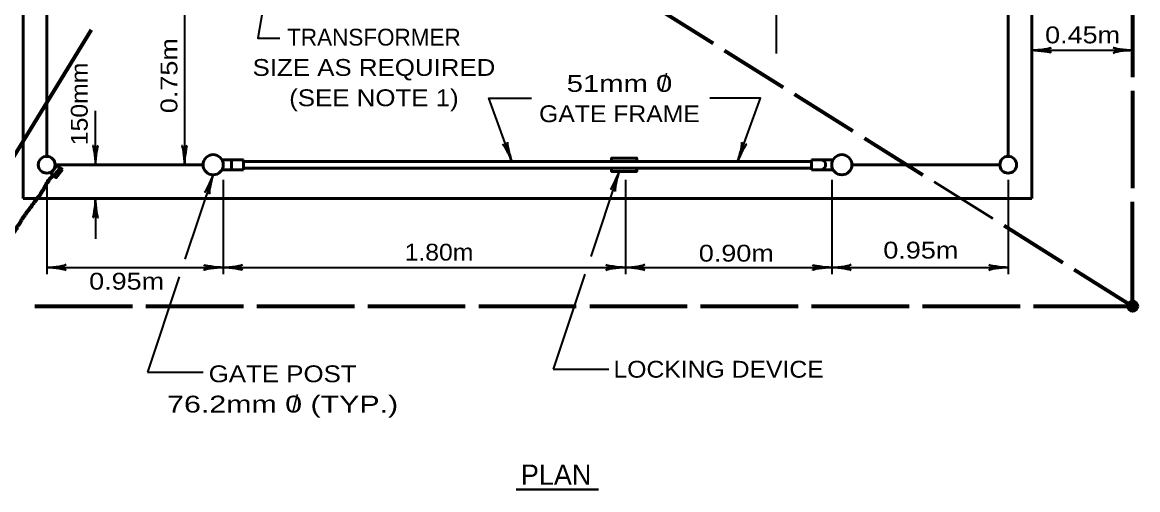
# Model space of a CAD drawing. Extents: x -30 to 826, y -11 to 533.
# Drawn here: x 133.1 to 332.2, y 286.6 to 369.9 of the extents above; entities that cross this region are included whole.
import ezdxf
from ezdxf.enums import TextEntityAlignment as Align

# ---------------------------------------------------------------- set-up
doc = ezdxf.new("R2010")
doc.units = 0
doc.header["$LTSCALE"] = 1.2
doc.layers.add('1', color=7, linetype='Continuous', lineweight=53)

msp = doc.modelspace()

# ---------------------------------------------------------------- hatches: boundary and pattern name
at = {"layer": '1'}
msp.add_hatch(color=256, dxfattribs=at).paths.add_polyline_path([(332.199, 319.332, 1), (330.399, 319.332, 1)])

# ---------------------------------------------------------------- linework, layer by layer
for p, q in [((133.299, 459.732), (133.299, 338.532)), ((313.299, 459.732), (313.299, 338.532)), ((137.499, 454.032), (137.499, 346.032)), ((309.099, 454.032), (309.099, 346.032)), ((138.999, 344.532), (165.399, 344.532)), ((172.599, 345.432), (168.758, 345.432)), ((170.499, 345.432), (170.499, 343.632)), ((172.599, 345.432), (172.599, 343.632)), ((273.999, 345.432), (273.999, 343.632)), ((273.999, 345.432), (277.84, 345.432)), ((281.199, 344.532), (307.599, 344.532)), ((172.599, 343.632), (168.758, 343.632)), ((273.999, 343.632), (277.84, 343.632)), ((295.895, 341.487), (306.34, 334.951)), ((133.299, 338.532), (313.299, 338.532))]:
    msp.add_line(p, q, dxfattribs=at)
at = {"layer": '1', "lineweight": 70}
for p, q in [((331.299, 377.532), (331.299, 360.132)), ((245.978, 372.723), (256.423, 366.187)), ((145.422, 368.559), (130.987, 344.969)), ((258.457, 364.914), (268.902, 358.378)), ((270.937, 357.105), (281.382, 350.569)), ((331.299, 357.732), (331.299, 340.332)), ((283.416, 349.296), (293.861, 342.76)), ((331.299, 319.332), (331.299, 337.932)), ((308.375, 333.677), (318.819, 327.141)), ((320.854, 325.868), (331.299, 319.332)), ((135.399, 319.332), (152.799, 319.332)), ((155.199, 319.332), (172.599, 319.332)), ((174.999, 319.332), (192.399, 319.332)), ((194.799, 319.332), (212.199, 319.332)), ((214.599, 319.332), (231.999, 319.332)), ((234.399, 319.332), (251.799, 319.332)), ((254.199, 319.332), (271.599, 319.332)), ((273.999, 319.332), (291.399, 319.332)), ((293.799, 319.332), (311.199, 319.332)), ((313.599, 319.332), (331.299, 319.332))]:
    msp.add_line(p, q, dxfattribs=at)
at = {"layer": '1', "lineweight": 35}
for p, q in [((162.099, 375.132), (162.099, 344.532)), ((267.699, 375.132), (267.699, 364.332)), ((313.299, 364.932), (331.299, 364.932)), ((146.199, 344.532), (146.199, 354.132)), ((167.199, 342.732), (162.177, 327.69)), ((239.627, 343.221), (234.606, 328.179)), ((137.499, 341.832), (137.499, 325.032)), ((168.999, 341.832), (168.999, 325.032)), ((240.762, 341.832), (240.762, 325.032)), ((277.599, 341.832), (277.599, 325.032)), ((309.099, 341.832), (309.099, 325.032)), ((146.199, 338.532), (146.199, 331.332)), ((161.132, 324.561), (155.469, 307.596)), ((233.561, 325.05), (227.897, 308.085)), ((155.469, 307.596), (165.408, 307.596)), ((227.897, 308.085), (237.837, 308.085))]:
    msp.add_line(p, q, dxfattribs=at)
at = {"layer": '1', "lineweight": 40}
msp.add_line((221.301, 286.633), (235.959, 286.633), dxfattribs=at)
at = {"layer": '1', "lineweight": 35}
for points in [[(177.099, 378.132), (175.149, 367.075), (179.094, 367.075)], [(220.485, 345.132), (216.381, 356.409), (224.018, 356.409)], [(260.799, 345.132), (264.903, 356.409), (255.852, 356.409)], [(137.499, 326.232), (168.999, 326.232), (240.762, 326.232), (277.599, 326.232), (309.099, 326.232)]]:
    msp.add_lwpolyline(points, dxfattribs=at)
at = {"layer": '1'}
for points in [[(140.319, 343.64), (139.215, 342.218), (138.267, 342.953), (139.37, 344.375), (140.319, 343.64)], [(238.299, 345.132), (238.299, 345.732), (242.799, 345.732), (242.799, 345.132)], [(238.299, 343.932), (242.799, 343.932), (242.799, 343.332), (238.299, 343.332)]]:
    msp.add_lwpolyline(points, close=True, dxfattribs=at)
for points in [[(172.599, 345.132), (242.799, 345.132), (273.999, 345.132)], [(172.599, 343.932), (242.799, 343.932), (273.999, 343.932)]]:
    msp.add_lwpolyline(points, dxfattribs=at)
for centre, radius in [((137.499, 344.532), 1.5), ((167.199, 344.532), 1.8), ((279.399, 344.532), 1.8), ((309.099, 344.532), 1.5), ((331.299, 319.332), 0.9)]:
    msp.add_circle(centre, radius, dxfattribs=at)
msp.add_arc((275.583, 344.532), 0.925, 283.46774, 76.53226, dxfattribs=at)
at = {"layer": '1', "lineweight": 40}
for centre, major_axis, ratio, start_param, end_param in [((314.643, 364.678), (-2.108, 0.211), 0.07063, 3.1407148, 5.41811), ((314.608, 365.264), (-2.143, -0.187), 0.122415, 0.8963533, 3.1415927), ((329.989, 364.601), (2.143, 0.187), 0.122415, 0.8963533, 3.1415927), ((329.954, 365.186), (2.108, -0.211), 0.07063, 3.1407148, 5.41811), ((220.264, 346.483), (-0.523, 2.053), 0.07063, 6.2823074, 8.5597026), ((220.264, 346.483), (-0.523, 2.053), 0.07063, 6.2823074, 8.5597026), ((260.935, 346.476), (-0.557, -2.078), 0.122415, 0.8963533, 3.1415927), ((145.867, 345.842), (0.187, -2.143), 0.122415, 0.8963533, 3.1415927), ((146.453, 345.877), (-0.211, -2.108), 0.07063, 3.1407148, 5.41811), ((161.767, 345.842), (0.187, -2.143), 0.122415, 0.8963533, 3.1415927), ((162.353, 345.877), (-0.211, -2.108), 0.07063, 3.1407148, 5.41811), ((219.726, 346.249), (0.909, -1.95), 0.122415, 0.8963533, 3.1415927), ((219.726, 346.249), (0.909, -1.95), 0.122415, 0.8963533, 3.1415927), ((261.497, 346.309), (0.919, 1.909), 0.07063, 6.2823074, 8.5597026), ((166.532, 341.537), (-0.867, -1.933), 0.07063, 6.2823074, 8.5597026), ((167.099, 341.385), (0.501, 2.092), 0.122415, 0.8963533, 3.1415927), ((238.961, 342.026), (-0.867, -1.933), 0.07063, 6.2823074, 8.5597026), ((239.527, 341.874), (0.501, 2.092), 0.122415, 0.8963533, 3.1415927), ((145.945, 337.188), (0.211, 2.108), 0.07063, 3.1407148, 5.41811), ((146.53, 337.223), (-0.187, 2.143), 0.122415, 0.8963533, 3.1415927), ((138.808, 326.564), (-2.143, -0.187), 0.122415, 0.8963533, 3.1415927), ((167.654, 326.486), (2.108, -0.211), 0.07063, 3.1407148, 5.41811), ((167.654, 326.486), (2.108, -0.211), 0.07063, 3.1407148, 5.41811), ((170.308, 326.564), (-2.143, -0.187), 0.122415, 0.8963533, 3.1415927), ((170.308, 326.564), (-2.143, -0.187), 0.122415, 0.8963533, 3.1415927), ((239.417, 326.486), (2.108, -0.211), 0.07063, 3.1407148, 5.41811), ((239.417, 326.486), (2.108, -0.211), 0.07063, 3.1407148, 5.41811), ((242.071, 326.564), (-2.143, -0.187), 0.122415, 0.8963533, 3.1415927), ((242.071, 326.564), (-2.143, -0.187), 0.122415, 0.8963533, 3.1415927), ((276.254, 326.486), (2.108, -0.211), 0.07063, 3.1407148, 5.41811), ((276.254, 326.486), (2.108, -0.211), 0.07063, 3.1407148, 5.41811), ((278.908, 326.564), (-2.143, -0.187), 0.122415, 0.8963533, 3.1415927), ((278.908, 326.564), (-2.143, -0.187), 0.122415, 0.8963533, 3.1415927), ((307.754, 326.486), (2.108, -0.211), 0.07063, 3.1407148, 5.41811), ((138.843, 325.978), (-2.108, 0.211), 0.07063, 3.1407148, 5.41811), ((167.689, 325.901), (2.143, 0.187), 0.122415, 0.8963533, 3.1415927), ((167.689, 325.901), (2.143, 0.187), 0.122415, 0.8963533, 3.1415927), ((170.343, 325.978), (-2.108, 0.211), 0.07063, 3.1407148, 5.41811), ((170.343, 325.978), (-2.108, 0.211), 0.07063, 3.1407148, 5.41811), ((239.452, 325.901), (2.143, 0.187), 0.122415, 0.8963533, 3.1415927), ((239.452, 325.901), (2.143, 0.187), 0.122415, 0.8963533, 3.1415927), ((242.106, 325.978), (-2.108, 0.211), 0.07063, 3.1407148, 5.41811), ((242.106, 325.978), (-2.108, 0.211), 0.07063, 3.1407148, 5.41811), ((276.289, 325.901), (2.143, 0.187), 0.122415, 0.8963533, 3.1415927), ((276.289, 325.901), (2.143, 0.187), 0.122415, 0.8963533, 3.1415927), ((278.943, 325.978), (-2.108, 0.211), 0.07063, 3.1407148, 5.41811), ((278.943, 325.978), (-2.108, 0.211), 0.07063, 3.1407148, 5.41811), ((307.789, 325.901), (2.143, 0.187), 0.122415, 0.8963533, 3.1415927)]:
    msp.add_ellipse(centre, major_axis=major_axis, ratio=ratio, start_param=start_param, end_param=end_param, dxfattribs=at)
at = {"layer": '1', "lineweight": 70}
msp.add_spline([(139.942, 344.134), (139.815, 343.853), (139.688, 343.604), (139.562, 343.417), (139.405, 343.262), (139.185, 343.044), (138.996, 342.857), (138.839, 342.733), (138.619, 342.578), (138.399, 342.392), (138.179, 342.174), (138.021, 341.956), (137.832, 341.77), (137.674, 341.458), (137.548, 341.302), (137.422, 341.115), (137.327, 340.929), (137.138, 340.617), (136.979, 340.274), (136.79, 339.962), (136.632, 339.744), (136.443, 339.433), (136.222, 339.059), (135.97, 338.748), (135.686, 338.374), (135.465, 338.063), (135.339, 337.907), (135.213, 337.72), (134.993, 337.471), (134.867, 337.316), (134.772, 337.097), (134.551, 336.849), (134.425, 336.662), (134.268, 336.444), (134.141, 336.288), (133.953, 336.102), (133.827, 335.915), (133.637, 335.634), (133.511, 335.447), (133.322, 335.23), (133.196, 334.98), (133.038, 334.731), (132.848, 334.42), (132.69, 334.17), (132.532, 333.89), (132.344, 333.672), (132.186, 333.392), (132.027, 333.08), (131.901, 332.862), (131.775, 332.644), (131.586, 332.394), (131.459, 332.176), (131.333, 331.99), (131.275, 331.903)], degree=3, dxfattribs=at)

# ---------------------------------------------------------------- texts
at = {"layer": '1'}
msp.add_text('TRANSFORMER', height=3, dxfattribs=at).set_placement((195.897, 365.769), align=Align.CENTER)
for s, width, p in [('0.45m', 1.2, (315.672, 366.169)), ('1.80m', 1.1, (201.375, 327.454)), ('0.95m', 1.2, (286.803, 327.82)), ('0.90m', 1.2, (253.876, 327.271)), ('0.95m', 1.2, (145.073, 322.278)), ('LOCKING DEVICE', 1.1, (238.647, 306.591))]:
    msp.add_text(s, height=3, dxfattribs=dict(at, width=width)).set_placement(p)
for s, width, p in [('0.75m', 1.2, (160.816, 353.715)), ('150mm', 1.1, (144.813, 348.013))]:
    msp.add_text(s, height=3, rotation=90, dxfattribs=dict(at, width=width)).set_placement(p)
for s, width, p in [('SIZE AS REQUIRED', 1.15, (195.897, 360.369)), ('51mm 0', 1.3, (239.715, 357.522)), ('(SEE NOTE 1)', 1.15, (195.897, 354.969)), ('GATE FRAME', 1.1, (239.715, 352.122)), ('GATE POST', 1.15, (179.606, 305.78)), ('76.2mm 0 (TYP.)', 1.35, (179.606, 300.38))]:
    msp.add_text(s, height=3, dxfattribs=dict(at, width=width)).set_placement(p, align=Align.CENTER)
for s, height, p in [('/', 3, (247.161, 357.729)), ('/', 3, (181.268, 300.433)), ('PLAN', 3.6, (222.12, 287.5))]:
    msp.add_text(s, height=height, dxfattribs=at).set_placement(p)

doc.saveas('drawing.dxf')
